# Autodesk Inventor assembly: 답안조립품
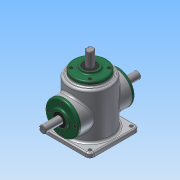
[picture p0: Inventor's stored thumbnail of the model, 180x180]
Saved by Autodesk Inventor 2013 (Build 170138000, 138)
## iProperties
Created: 2015-10
Part Number: 답안조립품
Document SubType Name: Assembly
Designer: Administrator
Author: Administrator
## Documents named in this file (14)
- C:\Users\Administrator\Desktop\451008V1013\답안조립품.iam
- C:\Users\Administrator\Desktop\451008V1013\본체.ipt
- C:\Users\Administrator\Desktop\451008V1013\커버.ipt
- C:\Users\Administrator\Desktop\451008V1013\M4.ipt
- C:\Users\Administrator\Desktop\451008V1013\베어링 6203.ipt
- C:\Users\Administrator\Desktop\451008V1013\오일실.ipt
- C:\Users\Administrator\Desktop\451008V1013\메인 축.ipt
- 메인 축.ipt
- C:\Users\Administrator\Desktop\451008V1013\키 5x5.ipt
- C:\Users\Administrator\Desktop\451008V1013\메인 베벨기어.ipt
- C:\Users\Administrator\Desktop\451008V1013\서브 축.ipt
- 서브 축.ipt
- C:\Users\Administrator\Desktop\451008V1013\서브 베벨기어.ipt
- C:\Users\Administrator\Desktop\451008V1013\키 4x4.ipt
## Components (12 placed, 1 different names)
1. M4:1
2. M4:4
3. M4:5
4. M4:6
5. M4:2
6. M4:7
7. M4:8
8. M4:9
9. M4:3
10. M4:10
11. M4:11
12. M4:12
